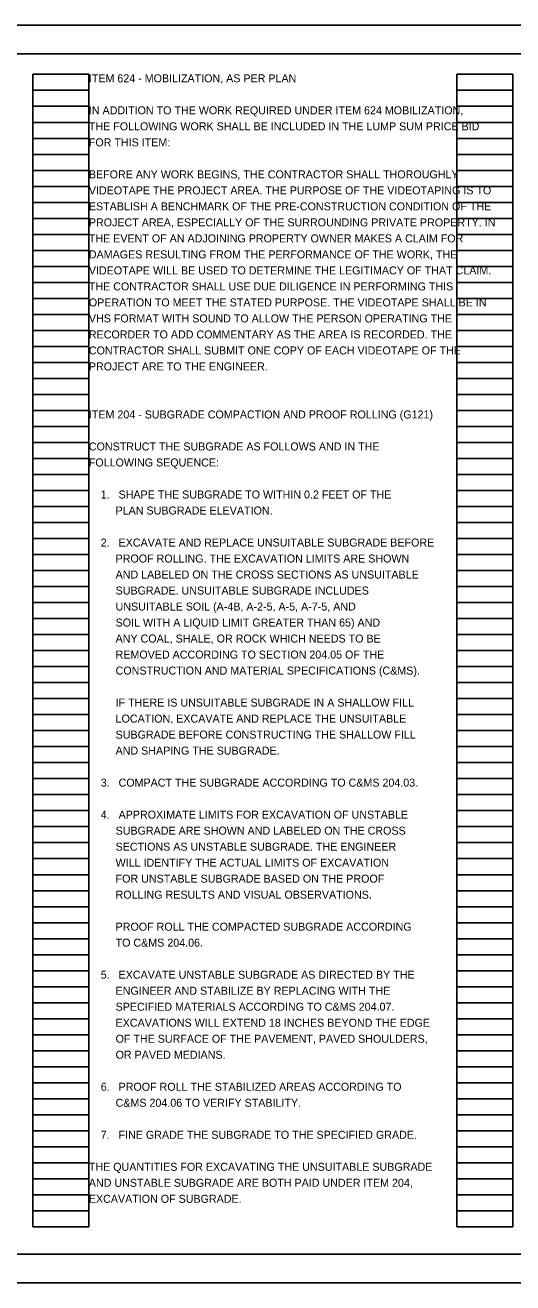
# Model space of a CAD drawing. Extents: x 0 to 46.4, y 0 to 22.
# Drawn here: x 16.13 to 24.66, y 0 to 22 of the extents above; entities that cross this region are included whole.
import ezdxf

# ---------------------------------------------------------------- set-up
doc = ezdxf.new("R2010")
doc.units = 0
for name, color, linetype in [('SH_Border', 7, 'Continuous'), ('SH_Cut_Line', 7, 'Continuous'), ('SH_Data', 7, 'Continuous'), ('SH_Text', 7, 'Continuous')]:
    doc.layers.add(name, color=color, linetype=linetype)

msp = doc.modelspace()

# ---------------------------------------------------------------- linework, layer by layer
at = {"layer": 'SH_Border'}
msp.add_lwpolyline([(1.5, 21.5), (33.5, 21.5), (33.5, 0.5), (1.5, 0.5)], close=True, dxfattribs=at)
at = {"layer": 'SH_Cut_Line'}
msp.add_lwpolyline([(0, 0), (34, 0), (34, 22), (0, 22)], close=True, dxfattribs=at)
at = {"layer": 'SH_Data'}
for p, q in [((16.26, 0.98), (16.26, 21.14)), ((16.26, 21.14), (17.24, 21.14)), ((17.24, 0.98), (17.24, 21.14)), ((23.68, 0.98), (23.68, 21.14)), ((23.68, 21.14), (24.66, 21.14)), ((24.66, 0.98), (24.66, 21.14)), ((16.26, 20.86), (17.24, 20.86)), ((23.68, 20.86), (24.66, 20.86)), ((16.26, 20.58), (17.24, 20.58)), ((23.68, 20.58), (24.66, 20.58)), ((16.26, 20.3), (17.24, 20.3)), ((23.68, 20.3), (24.66, 20.3)), ((16.26, 20.02), (17.24, 20.02)), ((23.68, 20.02), (24.66, 20.02)), ((16.26, 19.74), (17.24, 19.74)), ((23.68, 19.74), (24.66, 19.74)), ((16.26, 19.46), (17.24, 19.46)), ((23.68, 19.46), (24.66, 19.46)), ((16.26, 19.18), (17.24, 19.18)), ((23.68, 19.18), (24.66, 19.18)), ((16.26, 18.9), (17.24, 18.9)), ((23.68, 18.9), (24.66, 18.9)), ((16.26, 18.62), (17.24, 18.62)), ((23.68, 18.62), (24.66, 18.62)), ((16.26, 18.34), (17.24, 18.34)), ((23.68, 18.34), (24.66, 18.34)), ((16.26, 18.06), (17.24, 18.06)), ((23.68, 18.06), (24.66, 18.06)), ((16.26, 17.78), (17.24, 17.78)), ((23.68, 17.78), (24.66, 17.78)), ((16.26, 17.5), (17.24, 17.5)), ((23.68, 17.5), (24.66, 17.5)), ((16.26, 17.22), (17.24, 17.22)), ((23.68, 17.22), (24.66, 17.22)), ((16.26, 16.94), (17.24, 16.94)), ((23.68, 16.94), (24.66, 16.94)), ((16.26, 16.66), (17.24, 16.66)), ((23.68, 16.66), (24.66, 16.66)), ((16.26, 16.38), (17.24, 16.38)), ((23.68, 16.38), (24.66, 16.38)), ((16.26, 16.1), (17.24, 16.1)), ((23.68, 16.1), (24.66, 16.1)), ((16.26, 15.82), (17.24, 15.82)), ((23.68, 15.82), (24.66, 15.82)), ((16.26, 15.54), (17.24, 15.54)), ((23.68, 15.54), (24.66, 15.54)), ((16.26, 15.26), (17.24, 15.26)), ((23.68, 15.26), (24.66, 15.26)), ((16.26, 14.98), (17.24, 14.98)), ((23.68, 14.98), (24.66, 14.98)), ((16.26, 14.7), (17.24, 14.7)), ((23.68, 14.7), (24.66, 14.7)), ((16.26, 14.42), (17.24, 14.42)), ((23.68, 14.42), (24.66, 14.42)), ((16.26, 14.14), (17.24, 14.14)), ((23.68, 14.14), (24.66, 14.14)), ((16.26, 13.86), (17.24, 13.86)), ((23.68, 13.86), (24.66, 13.86)), ((16.26, 13.58), (17.24, 13.58)), ((23.68, 13.58), (24.66, 13.58)), ((16.26, 13.3), (17.24, 13.3)), ((23.68, 13.3), (24.66, 13.3)), ((16.26, 13.02), (17.24, 13.02)), ((23.68, 13.02), (24.66, 13.02)), ((16.26, 12.74), (17.24, 12.74)), ((23.68, 12.74), (24.66, 12.74)), ((16.26, 12.46), (17.24, 12.46)), ((23.68, 12.46), (24.66, 12.46)), ((16.26, 12.18), (17.24, 12.18)), ((23.68, 12.18), (24.66, 12.18)), ((16.26, 11.9), (17.24, 11.9)), ((23.68, 11.9), (24.66, 11.9)), ((16.26, 11.62), (17.24, 11.62)), ((23.68, 11.62), (24.66, 11.62)), ((16.26, 11.34), (17.24, 11.34)), ((23.68, 11.34), (24.66, 11.34)), ((16.26, 11.06), (17.24, 11.06)), ((23.68, 11.06), (24.66, 11.06)), ((16.26, 10.78), (17.24, 10.78)), ((23.68, 10.78), (24.66, 10.78)), ((16.26, 10.5), (17.24, 10.5)), ((23.68, 10.5), (24.66, 10.5)), ((16.26, 10.22), (17.24, 10.22)), ((23.68, 10.22), (24.66, 10.22)), ((16.26, 9.94), (17.24, 9.94)), ((23.68, 9.94), (24.66, 9.94)), ((16.26, 9.66), (17.24, 9.66)), ((23.68, 9.66), (24.66, 9.66)), ((16.26, 9.38), (17.24, 9.38)), ((23.68, 9.38), (24.66, 9.38)), ((16.26, 9.1), (17.24, 9.1)), ((23.68, 9.1), (24.66, 9.1)), ((16.26, 8.82), (17.24, 8.82)), ((23.68, 8.82), (24.66, 8.82)), ((16.26, 8.54), (17.24, 8.54)), ((23.68, 8.54), (24.66, 8.54)), ((16.26, 8.26), (17.24, 8.26)), ((23.68, 8.26), (24.66, 8.26)), ((16.26, 7.98), (17.24, 7.98)), ((23.68, 7.98), (24.66, 7.98)), ((16.26, 7.7), (17.24, 7.7)), ((23.68, 7.7), (24.66, 7.7)), ((16.26, 7.42), (17.24, 7.42)), ((23.68, 7.42), (24.66, 7.42)), ((16.26, 7.14), (17.24, 7.14)), ((23.68, 7.14), (24.66, 7.14)), ((16.26, 6.86), (17.24, 6.86)), ((23.68, 6.86), (24.66, 6.86)), ((16.26, 6.58), (17.24, 6.58)), ((23.68, 6.58), (24.66, 6.58)), ((16.26, 6.3), (17.24, 6.3)), ((23.68, 6.3), (24.66, 6.3)), ((16.26, 6.02), (17.24, 6.02)), ((23.68, 6.02), (24.66, 6.02)), ((16.26, 5.74), (17.24, 5.74)), ((23.68, 5.74), (24.66, 5.74)), ((16.26, 5.46), (17.24, 5.46)), ((23.68, 5.46), (24.66, 5.46)), ((16.26, 5.18), (17.24, 5.18)), ((23.68, 5.18), (24.66, 5.18)), ((16.26, 4.9), (17.24, 4.9)), ((23.68, 4.9), (24.66, 4.9)), ((16.26, 4.62), (17.24, 4.62)), ((23.68, 4.62), (24.66, 4.62)), ((16.26, 4.34), (17.24, 4.34)), ((23.68, 4.34), (24.66, 4.34)), ((16.26, 4.06), (17.24, 4.06)), ((23.68, 4.06), (24.66, 4.06)), ((16.26, 3.78), (17.24, 3.78)), ((23.68, 3.78), (24.66, 3.78)), ((16.26, 3.5), (17.24, 3.5)), ((23.68, 3.5), (24.66, 3.5)), ((16.26, 3.22), (17.24, 3.22)), ((23.68, 3.22), (24.66, 3.22)), ((16.26, 2.94), (17.24, 2.94)), ((23.68, 2.94), (24.66, 2.94)), ((16.26, 2.66), (17.24, 2.66)), ((23.68, 2.66), (24.66, 2.66)), ((16.26, 2.38), (17.24, 2.38)), ((23.68, 2.38), (24.66, 2.38)), ((16.26, 2.1), (17.24, 2.1)), ((23.68, 2.1), (24.66, 2.1)), ((16.26, 1.82), (17.24, 1.82)), ((23.68, 1.82), (24.66, 1.82)), ((16.26, 1.54), (17.24, 1.54)), ((23.68, 1.54), (24.66, 1.54)), ((16.26, 1.26), (17.24, 1.26)), ((23.68, 1.26), (24.66, 1.26)), ((16.26, 0.98), (17.24, 0.98)), ((23.68, 0.98), (24.66, 0.98))]:
    msp.add_line(p, q, dxfattribs=at)

# ---------------------------------------------------------------- texts
at = {"layer": 'SH_Text'}
for s, p in [('ITEM 624 - MOBILIZATION, AS PER PLAN', (17.24, 21)), ('IN ADDITION TO THE WORK REQUIRED UNDER ITEM 624 MOBILIZATION, ', (17.24, 20.44)), ('THE FOLLOWING WORK SHALL BE INCLUDED IN THE LUMP SUM PRICE BID ', (17.24, 20.16)), ('FOR THIS ITEM:', (17.24, 19.88)), ('BEFORE ANY WORK BEGINS, THE CONTRACTOR SHALL THOROUGHLY ', (17.24, 19.32)), ('VIDEOTAPE THE PROJECT AREA. THE PURPOSE OF THE VIDEOTAPING IS TO ', (17.24, 19.04)), ('ESTABLISH A BENCHMARK OF THE PRE-CONSTRUCTION CONDITION OF THE ', (17.24, 18.76)), ('PROJECT AREA, ESPECIALLY OF THE SURROUNDING PRIVATE PROPERTY. IN ', (17.24, 18.48)), ('THE EVENT OF AN ADJOINING PROPERTY OWNER MAKES A CLAIM FOR ', (17.24, 18.2)), ('DAMAGES RESULTING FROM THE PERFORMANCE OF THE WORK, THE ', (17.24, 17.92)), ('VIDEOTAPE WILL BE USED TO DETERMINE THE LEGITIMACY OF THAT CLAIM. ', (17.24, 17.64)), ('THE CONTRACTOR SHALL USE DUE DILIGENCE IN PERFORMING THIS ', (17.24, 17.36)), ('OPERATION TO MEET THE STATED PURPOSE. THE VIDEOTAPE SHALL BE IN ', (17.24, 17.08)), ('VHS FORMAT WITH SOUND TO ALLOW THE PERSON OPERATING THE ', (17.24, 16.8)), ('RECORDER TO ADD COMMENTARY AS THE AREA IS RECORDED. THE ', (17.24, 16.52)), ('CONTRACTOR SHALL SUBMIT ONE COPY OF EACH VIDEOTAPE OF THE ', (17.24, 16.24)), ('PROJECT ARE TO THE ENGINEER.', (17.24, 15.96)), ('ITEM 204 - SUBGRADE COMPACTION AND PROOF ROLLING (G121)', (17.24, 15.12)), ('CONSTRUCT THE SUBGRADE AS FOLLOWS AND IN THE', (17.24, 14.56)), ('FOLLOWING SEQUENCE:', (17.24, 14.28)), ('    1.   SHAPE THE SUBGRADE TO WITHIN 0.2 FEET OF THE', (17.24, 13.72)), ('         PLAN SUBGRADE ELEVATION.', (17.24, 13.44)), ('    2.   EXCAVATE AND REPLACE UNSUITABLE SUBGRADE BEFORE', (17.24, 12.88)), ('         PROOF ROLLING. THE EXCAVATION LIMITS ARE SHOWN', (17.24, 12.6)), ('         AND LABELED ON THE CROSS SECTIONS AS UNSUITABLE', (17.24, 12.32)), ('         SUBGRADE. UNSUITABLE SUBGRADE INCLUDES', (17.24, 12.04)), ('         UNSUITABLE SOIL (A-4B, A-2-5, A-5, A-7-5, AND', (17.24, 11.76)), ('         SOIL WITH A LIQUID LIMIT GREATER THAN 65) AND', (17.24, 11.48)), ('         ANY COAL, SHALE, OR ROCK WHICH NEEDS TO BE', (17.24, 11.2)), ('         REMOVED ACCORDING TO SECTION 204.05 OF THE', (17.24, 10.92)), ('         CONSTRUCTION AND MATERIAL SPECIFICATIONS (C&MS).', (17.24, 10.64)), ('         IF THERE IS UNSUITABLE SUBGRADE IN A SHALLOW FILL', (17.24, 10.08)), ('         LOCATION, EXCAVATE AND REPLACE THE UNSUITABLE', (17.24, 9.8)), ('         SUBGRADE BEFORE CONSTRUCTING THE SHALLOW FILL', (17.24, 9.52)), ('         AND SHAPING THE SUBGRADE.', (17.24, 9.24)), ('    3.   COMPACT THE SUBGRADE ACCORDING TO C&MS 204.03.', (17.24, 8.68)), ('    4.   APPROXIMATE LIMITS FOR EXCAVATION OF UNSTABLE', (17.24, 8.12)), ('         SUBGRADE ARE SHOWN AND LABELED ON THE CROSS', (17.24, 7.84)), ('         SECTIONS AS UNSTABLE SUBGRADE. THE ENGINEER', (17.24, 7.56)), ('         WILL IDENTIFY THE ACTUAL LIMITS OF EXCAVATION', (17.24, 7.28)), ('         FOR UNSTABLE SUBGRADE BASED ON THE PROOF', (17.24, 7)), ('         ROLLING RESULTS AND VISUAL OBSERVATIONS.', (17.24, 6.72)), ('         PROOF ROLL THE COMPACTED SUBGRADE ACCORDING', (17.24, 6.16)), ('         TO C&MS 204.06.', (17.24, 5.88)), ('    5.   EXCAVATE UNSTABLE SUBGRADE AS DIRECTED BY THE', (17.24, 5.32)), ('         ENGINEER AND STABILIZE BY REPLACING WITH THE', (17.24, 5.04)), ('         SPECIFIED MATERIALS ACCORDING TO C&MS 204.07.', (17.24, 4.76)), ('         EXCAVATIONS WILL EXTEND 18 INCHES BEYOND THE EDGE', (17.24, 4.48)), ('         OF THE SURFACE OF THE PAVEMENT, PAVED SHOULDERS,', (17.24, 4.2)), ('         OR PAVED MEDIANS.', (17.24, 3.92)), ('    6.   PROOF ROLL THE STABILIZED AREAS ACCORDING TO', (17.24, 3.36)), ('         C&MS 204.06 TO VERIFY STABILITY.', (17.24, 3.08)), ('    7.   FINE GRADE THE SUBGRADE TO THE SPECIFIED GRADE.', (17.24, 2.52)), ('THE QUANTITIES FOR EXCAVATING THE UNSUITABLE SUBGRADE', (17.24, 1.96)), ('AND UNSTABLE SUBGRADE ARE BOTH PAID UNDER ITEM 204,', (17.24, 1.68)), ('EXCAVATION OF SUBGRADE.', (17.24, 1.4))]:
    msp.add_text(s, height=0.14, dxfattribs=at).set_placement(p)

doc.saveas('drawing.dxf')
